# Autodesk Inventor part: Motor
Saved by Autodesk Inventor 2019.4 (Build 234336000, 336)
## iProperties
Created: 2020-06
Part Number: Motor
Material: Generic
Document SubType Name: Modeling
Designer: Administrator
Density: 1 g/cm^3
Appearance: Default
Title: Motor v5
Author: Administrator
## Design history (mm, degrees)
feature "Motor"
body "Solid1"
